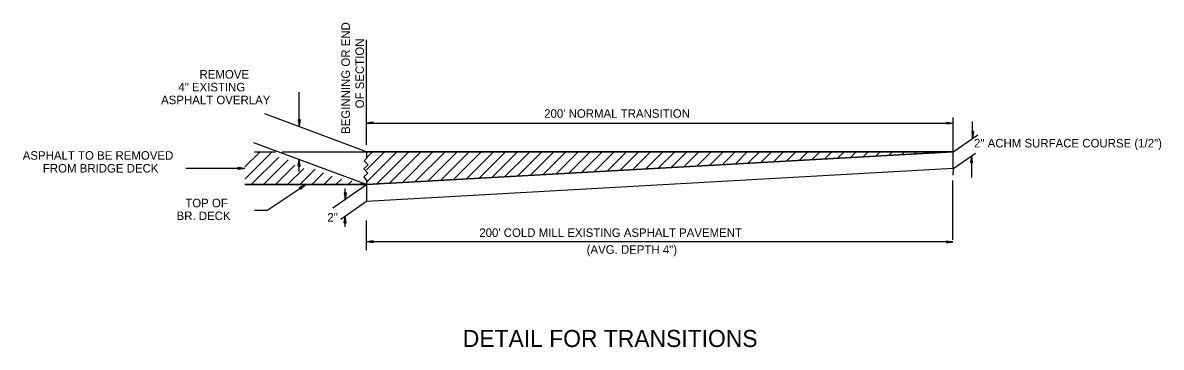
# Model space of a CAD drawing. Extents: x 1931522 to 1935523, y 600380 to 605075.
# Drawn here: x 1934724 to 1935523, y 602530 to 602758 of the extents above; entities that cross this region are included whole.
import ezdxf

# ---------------------------------------------------------------- set-up
doc = ezdxf.new("R2010")
doc.units = 0
doc.layers.add('Default', color=7, linetype='Continuous')
doc.layers.add('R_Border', color=7, linetype='Continuous')

msp = doc.modelspace()

# ---------------------------------------------------------------- linework, layer by layer
at = {"layer": 'Default'}
for p, q in [((1934964.92, 602672.28), (1934964.92, 602746.21)), ((1934917.54, 602685.39), (1934917.54, 602709.38)), ((1934964.92, 602667.46), (1934893.38, 602694.17)), ((1934916.87, 602689.84), (1934917.54, 602685.39)), ((1934916.87, 602689.84), (1934917.54, 602686.06)), ((1934918.2, 602689.84), (1934916.87, 602689.84)), ((1934917.1, 602689.84), (1934917.54, 602686.95)), ((1934917.1, 602689.84), (1934917.54, 602687.61)), ((1934917.32, 602689.84), (1934917.54, 602688.5)), ((1934917.32, 602689.84), (1934917.54, 602689.16)), ((1934918.2, 602689.84), (1934917.54, 602685.39)), ((1934917.76, 602689.84), (1934917.54, 602688.5)), ((1934917.99, 602689.84), (1934917.54, 602686.95)), ((1934917.99, 602689.84), (1934917.54, 602686.06)), ((1934917.76, 602689.84), (1934917.54, 602687.61)), ((1934917.54, 602689.84), (1934917.54, 602689.16)), ((1935376.48, 602667.46), (1935376.48, 602691.67)), ((1935390.24, 602676.99), (1935390.24, 602688.76)), ((1934969.59, 602688.34), (1934964.92, 602687.68)), ((1934964.92, 602687.68), (1935376.48, 602687.68)), ((1934969.59, 602687.01), (1934964.92, 602687.68)), ((1934969.59, 602688.13), (1934965.6, 602687.68)), ((1934969.59, 602687.01), (1934965.6, 602687.68)), ((1934969.59, 602688.13), (1934966.49, 602687.68)), ((1934969.59, 602687.23), (1934966.49, 602687.68)), ((1934969.59, 602687.9), (1934967.38, 602687.68)), ((1934969.59, 602687.23), (1934967.38, 602687.68)), ((1934969.59, 602687.9), (1934968.04, 602687.68)), ((1934969.59, 602687.46), (1934968.04, 602687.68)), ((1934969.59, 602687.68), (1934968.93, 602687.68)), ((1934969.59, 602687.46), (1934968.93, 602687.68)), ((1934969.59, 602687.01), (1934969.59, 602688.34)), ((1935371.81, 602688.34), (1935376.48, 602687.68)), ((1935371.81, 602688.34), (1935371.81, 602687.01)), ((1935371.81, 602688.13), (1935374.93, 602687.68)), ((1935371.81, 602688.13), (1935375.58, 602687.68)), ((1935371.81, 602687.9), (1935373.36, 602687.68)), ((1935371.81, 602687.9), (1935374.04, 602687.68)), ((1935371.81, 602687.01), (1935376.48, 602687.68)), ((1935371.81, 602687.46), (1935373.36, 602687.68)), ((1935371.81, 602687.23), (1935374.93, 602687.68)), ((1935371.81, 602687.01), (1935375.58, 602687.68)), ((1935371.81, 602687.23), (1935374.04, 602687.68)), ((1935371.81, 602687.46), (1935372.48, 602687.68)), ((1935371.81, 602687.68), (1935372.48, 602687.68)), ((1935389.59, 602681.66), (1935390.24, 602676.99)), ((1935390.91, 602681.66), (1935389.59, 602681.66)), ((1935389.81, 602681.66), (1935390.24, 602678.55)), ((1935389.81, 602681.66), (1935390.24, 602677.89)), ((1935390.02, 602681.66), (1935390.24, 602680.11)), ((1935390.02, 602681.66), (1935390.24, 602679.44)), ((1935390.91, 602681.66), (1935390.24, 602676.99)), ((1935390.47, 602681.66), (1935390.24, 602680.11)), ((1935390.7, 602681.66), (1935390.24, 602678.55)), ((1935390.91, 602681.66), (1935390.24, 602677.89)), ((1935390.7, 602681.66), (1935390.24, 602679.44)), ((1935390.24, 602681.66), (1935390.24, 602680.99)), ((1935390.47, 602681.66), (1935390.24, 602680.99)), ((1934964.86, 602644.38), (1934885.78, 602673.83)), ((1935376.48, 602667.46), (1935393.8, 602679.44)), ((1934879.48, 602648.35), (1934898.58, 602667.46)), ((1934879.48, 602656.83), (1934890.1, 602667.46)), ((1934886.29, 602667.46), (1934900.93, 602667.46)), ((1934905.7, 602667.46), (1934915.16, 602667.46)), ((1934915.16, 602667.46), (1935376.48, 602667.46)), ((1934964.93, 602654.86), (1934977.53, 602667.46)), ((1934964.93, 602663.34), (1934969.05, 602667.46)), ((1934964.94, 602646.38), (1934986.02, 602667.46)), ((1934971.81, 602644.77), (1934994.5, 602667.46)), ((1934980.8, 602645.27), (1935002.99, 602667.46)), ((1934989.79, 602645.77), (1935011.47, 602667.46)), ((1934998.78, 602646.28), (1935019.96, 602667.46)), ((1935007.77, 602646.78), (1935028.44, 602667.46)), ((1935016.76, 602647.29), (1935036.93, 602667.46)), ((1935025.75, 602647.79), (1935045.41, 602667.46)), ((1935034.74, 602648.29), (1935053.9, 602667.46)), ((1935043.73, 602648.8), (1935062.38, 602667.46)), ((1935052.72, 602649.3), (1935070.87, 602667.46)), ((1935061.7, 602649.81), (1935079.35, 602667.46)), ((1935070.69, 602650.31), (1935087.84, 602667.46)), ((1935079.68, 602650.81), (1935096.33, 602667.46)), ((1935088.67, 602651.32), (1935104.81, 602667.46)), ((1935097.66, 602651.82), (1935113.3, 602667.46)), ((1935106.65, 602652.33), (1935121.78, 602667.46)), ((1935115.64, 602652.83), (1935130.27, 602667.46)), ((1935124.63, 602653.34), (1935138.75, 602667.46)), ((1935133.62, 602653.84), (1935147.24, 602667.46)), ((1935142.61, 602654.34), (1935155.72, 602667.46)), ((1935151.6, 602654.85), (1935164.21, 602667.46)), ((1935160.59, 602655.35), (1935172.69, 602667.46)), ((1935169.58, 602655.86), (1935181.18, 602667.46)), ((1935178.57, 602656.36), (1935189.66, 602667.46)), ((1935187.56, 602656.86), (1935198.15, 602667.46)), ((1935196.54, 602657.37), (1935206.63, 602667.46)), ((1935205.53, 602657.87), (1935215.12, 602667.46)), ((1935214.52, 602658.38), (1935223.6, 602667.46)), ((1935223.51, 602658.88), (1935232.09, 602667.46)), ((1935232.5, 602659.38), (1935240.57, 602667.46)), ((1935241.49, 602659.89), (1935249.06, 602667.46)), ((1935250.48, 602660.39), (1935257.55, 602667.46)), ((1935259.47, 602660.9), (1935266.03, 602667.46)), ((1935268.46, 602661.4), (1935274.52, 602667.46)), ((1935277.45, 602661.9), (1935283, 602667.46)), ((1935286.44, 602662.41), (1935291.49, 602667.46)), ((1935295.43, 602662.91), (1935299.97, 602667.46)), ((1935304.42, 602663.42), (1935308.46, 602667.46)), ((1935313.41, 602663.92), (1935316.94, 602667.46)), ((1935322.39, 602664.42), (1935325.43, 602667.46)), ((1935331.38, 602664.93), (1935333.91, 602667.46)), ((1935340.37, 602665.43), (1935342.4, 602667.46)), ((1935349.36, 602665.94), (1935350.88, 602667.46)), ((1935358.35, 602666.44), (1935359.37, 602667.46)), ((1935367.34, 602666.94), (1935367.85, 602667.46)), ((1935376.33, 602667.45), (1935376.34, 602667.46)), ((1935376.48, 602655.92), (1935376.48, 602667.46)), ((1935377.13, 602655.93), (1935392.23, 602666.59)), ((1935388.9, 602659.93), (1935389.56, 602664.6)), ((1935389.56, 602649.49), (1935389.56, 602664.6)), ((1935390.23, 602659.93), (1935389.56, 602664.6)), ((1934874.76, 602655.21), (1934874.81, 602656.62)), ((1934874.81, 602656.62), (1934879.48, 602655.92)), ((1934883.99, 602644.38), (1934903.32, 602663.71)), ((1934892.47, 602644.38), (1934909.93, 602661.83)), ((1934900.96, 602644.38), (1934914.57, 602657.98)), ((1934916.87, 602657.3), (1934917.54, 602661.97)), ((1934916.87, 602657.3), (1934917.54, 602661.3)), ((1934916.87, 602657.3), (1934918.2, 602657.3)), ((1934917.1, 602657.3), (1934917.54, 602660.42)), ((1934917.1, 602657.3), (1934917.54, 602659.76)), ((1934917.32, 602657.3), (1934917.54, 602658.86)), ((1934917.32, 602657.3), (1934917.54, 602657.97)), ((1934918.2, 602657.3), (1934917.54, 602661.97)), ((1934917.54, 602653.53), (1934917.54, 602661.97)), ((1934917.99, 602657.3), (1934917.54, 602661.3)), ((1934917.99, 602657.3), (1934917.54, 602660.42)), ((1934917.76, 602657.3), (1934917.54, 602659.76)), ((1934917.76, 602657.3), (1934917.54, 602658.86)), ((1934917.54, 602657.3), (1934917.54, 602657.97)), ((1935388.9, 602659.93), (1935390.23, 602659.93)), ((1935389.13, 602659.93), (1935389.56, 602663.93)), ((1935389.13, 602659.93), (1935389.56, 602663.03)), ((1935389.34, 602659.93), (1935389.56, 602662.37)), ((1935389.34, 602659.93), (1935389.56, 602661.47)), ((1935390.23, 602659.93), (1935389.56, 602663.93)), ((1935390.01, 602659.93), (1935389.56, 602663.03)), ((1935390.01, 602659.93), (1935389.56, 602662.37)), ((1935389.78, 602659.93), (1935389.56, 602661.47)), ((1935389.78, 602659.93), (1935389.56, 602660.83)), ((1935389.56, 602659.93), (1935389.56, 602660.83)), ((1934837.91, 602655.92), (1934879.48, 602655.92)), ((1934874.76, 602655.21), (1934879.48, 602655.92)), ((1934874.77, 602656.32), (1934877.88, 602655.85)), ((1934874.81, 602655.52), (1934876.46, 602655.9)), ((1934874.81, 602655.52), (1934877.07, 602655.81)), ((1934874.86, 602655.83), (1934875.65, 602655.87)), ((1934874.86, 602655.83), (1934875.65, 602655.87)), ((1934874.91, 602656.13), (1934876.46, 602655.9)), ((1934874.91, 602656.13), (1934877.07, 602655.81)), ((1934874.94, 602656.45), (1934878.68, 602655.89)), ((1934874.94, 602655.35), (1934878.68, 602655.89)), ((1934874.94, 602655.35), (1934877.88, 602655.85)), ((1934909.44, 602644.38), (1934920.81, 602655.75)), ((1934917.93, 602644.38), (1934928.86, 602655.31)), ((1934926.41, 602644.38), (1934934.74, 602652.7)), ((1934934.9, 602644.38), (1934940.76, 602650.23)), ((1934964.92, 602632.82), (1935376.48, 602655.92)), ((1935376.48, 602655.92), (1935376.28, 602650.96)), ((1934879.48, 602644.38), (1934964.86, 602644.38)), ((1934894.96, 602626.26), (1934922.17, 602644.38)), ((1934917.9, 602642.38), (1934922.17, 602644.38)), ((1934918.63, 602641.18), (1934917.9, 602642.38)), ((1934918.03, 602642.1), (1934920.88, 602643.44)), ((1934918.1, 602642.31), (1934921.52, 602643.91)), ((1934918.24, 602642.02), (1934920.22, 602642.95)), ((1934918.24, 602642.02), (1934919.67, 602642.69)), ((1934918.38, 602641.75), (1934919.01, 602642.22)), ((1934918.38, 602641.75), (1934919.01, 602642.22)), ((1934918.51, 602641.46), (1934920.22, 602642.95)), ((1934918.51, 602641.46), (1934919.67, 602642.69)), ((1934918.63, 602641.18), (1934922.17, 602644.38)), ((1934918.71, 602641.39), (1934921.52, 602643.91)), ((1934918.71, 602641.39), (1934920.88, 602643.44)), ((1934941.31, 602628.07), (1934964.86, 602644.38)), ((1934943.39, 602644.38), (1934947.28, 602648.27)), ((1934949.91, 602634), (1934949.91, 602641.57)), ((1934951.87, 602644.38), (1934954.54, 602647.04)), ((1934960.36, 602644.38), (1934961.58, 602645.6)), ((1935376.25, 602605.6), (1935376.25, 602647.25)), ((1934946.88, 602620.16), (1934964.86, 602632.83)), ((1934949.26, 602638.66), (1934949.91, 602634)), ((1934950.58, 602638.66), (1934949.26, 602638.66)), ((1934949.48, 602638.66), (1934949.91, 602635.56)), ((1934949.48, 602638.66), (1934949.91, 602634.89)), ((1934949.69, 602638.66), (1934949.91, 602637.12)), ((1934949.69, 602638.66), (1934949.91, 602636.45)), ((1934950.58, 602638.66), (1934949.91, 602634)), ((1934950.14, 602638.66), (1934949.91, 602637.12)), ((1934950.37, 602638.66), (1934949.91, 602635.56)), ((1934950.58, 602638.66), (1934949.91, 602634.89)), ((1934950.37, 602638.66), (1934949.91, 602636.45)), ((1934949.91, 602638.66), (1934949.91, 602638)), ((1934950.14, 602638.66), (1934949.91, 602638)), ((1934895.02, 602626.18), (1934886.25, 602626.18)), ((1934949.24, 602617.54), (1934949.9, 602622.21)), ((1934949.24, 602617.54), (1934950.57, 602617.54)), ((1934949.46, 602617.54), (1934949.9, 602621.54)), ((1934949.46, 602617.54), (1934949.9, 602620.64)), ((1934949.67, 602617.54), (1934949.9, 602619.98)), ((1934949.67, 602617.54), (1934949.9, 602619.08)), ((1934950.57, 602617.54), (1934949.9, 602622.21)), ((1934949.9, 602614.65), (1934949.9, 602622.21)), ((1934950.57, 602617.54), (1934949.9, 602621.54)), ((1934950.35, 602617.54), (1934949.9, 602620.64)), ((1934950.35, 602617.54), (1934949.9, 602619.98)), ((1934950.12, 602617.54), (1934949.9, 602619.08)), ((1934950.12, 602617.54), (1934949.9, 602618.43)), ((1934949.9, 602617.54), (1934949.9, 602618.43)), ((1934964.92, 602598.35), (1934964.92, 602619.15)), ((1934969.39, 602604.84), (1934964.92, 602604.19)), ((1935376.25, 602604.19), (1934964.92, 602604.19)), ((1934969.39, 602603.51), (1934964.92, 602604.19)), ((1934969.39, 602604.84), (1934965.6, 602604.19)), ((1934969.39, 602603.74), (1934965.6, 602604.19)), ((1934969.39, 602604.63), (1934966.49, 602604.19)), ((1934969.39, 602603.74), (1934966.49, 602604.19)), ((1934969.39, 602604.63), (1934967.15, 602604.19)), ((1934969.39, 602603.96), (1934967.15, 602604.19)), ((1934969.39, 602604.39), (1934968.04, 602604.19)), ((1934969.39, 602603.96), (1934968.04, 602604.19)), ((1934969.39, 602604.39), (1934968.71, 602604.19)), ((1934969.39, 602604.19), (1934968.71, 602604.19)), ((1934969.39, 602603.51), (1934969.39, 602604.84)), ((1935371.81, 602604.84), (1935376.25, 602604.19)), ((1935371.81, 602604.84), (1935375.58, 602604.19)), ((1935371.81, 602604.84), (1935371.81, 602603.51)), ((1935371.81, 602604.63), (1935374.7, 602604.19)), ((1935371.81, 602604.63), (1935374.04, 602604.19)), ((1935371.81, 602604.39), (1935373.15, 602604.19)), ((1935371.81, 602604.39), (1935372.48, 602604.19)), ((1935371.81, 602603.51), (1935376.25, 602604.19)), ((1935371.81, 602603.96), (1935373.15, 602604.19)), ((1935371.81, 602603.74), (1935374.7, 602604.19)), ((1935371.81, 602603.74), (1935375.58, 602604.19)), ((1935371.81, 602603.96), (1935374.04, 602604.19)), ((1935371.81, 602604.19), (1935372.48, 602604.19))]:
    msp.add_line(p, q, dxfattribs=at)
for points in [[(1934964.92, 602664.57), (1934964.92, 602662.82), (1934963.11, 602661.09), (1934965.89, 602658.21), (1934963.01, 602655.43), (1934965.78, 602652.55), (1934962.9, 602649.78), (1934964.87, 602647.26)], [(1934964.87, 602647.26), (1934964.86, 602644.38), (1935376.48, 602667.46), (1934964.92, 602667.45)], [(1934964.86, 602644.38), (1934964.92, 602632.82), (1935376.48, 602655.92), (1935376.48, 602667.46), (1934964.86, 602644.38)], [(1934964.86, 602644.38), (1934964.92, 602632.82), (1935376.48, 602655.92), (1935376.48, 602667.46), (1934964.86, 602644.38)], [(1934964.92, 602667.46), (1934964.92, 602664.57)], [(1934964.86, 602644.38), (1934879.48, 602644.38), (1934879.48, 602644.38)]]:
    msp.add_lwpolyline(points, dxfattribs=at)
at = {"layer": 'R_Border'}
msp.add_line((1934964.86, 602644.38), (1935376.48, 602667.46), dxfattribs=at)

# ---------------------------------------------------------------- texts
at = {"layer": 'Default'}
for s, height, rotation, p in [('BEGINNING OR END', 6, 90, (1934953.19, 602680.07)), ('OF SECTION', 6, 90, (1934963.05, 602698.02)), ('REMOVE', 6, 360, (1934847.64, 602718.92)), ('4" EXISTING ', 6, 360, (1934832.76, 602709.92)), ('ASPHALT OVERLAY', 6, 360, (1934820.67, 602700.92)), ("200' NORMAL TRANSITION ", 6, 360, (1935089.53, 602691.37)), ('2" ACHM SURFACE COURSE (1/2")', 6, 360, (1935391.21, 602670.52)), ('ASPHALT TO BE REMOVED', 6, 360, (1934723.57, 602661.89)), (' FROM BRIDGE DECK', 6, 360, (1934735.44, 602652.89)), ('TOP OF ', 6, 360, (1934837.63, 602628.48)), ('BR. DECK', 6, 360, (1934831.54, 602619.48)), ('2"', 6, 360, (1934937.32, 602618.43)), ("200' COLD MILL EXISTING ASPHALT PAVEMENT", 6, 360, (1935043.99, 602607.65)), ('(AVG. DEPTH 4")', 6, 360, (1935119.32, 602595.81)), ('DETAIL FOR TRANSITIONS', 12, 360, (1935032.42, 602530.3))]:
    msp.add_text(s, height=height, rotation=rotation, dxfattribs=at).set_placement(p)

doc.saveas('drawing.dxf')
